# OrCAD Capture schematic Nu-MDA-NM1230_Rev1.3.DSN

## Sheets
1 Connect: size A4; title: Nu-MDA-NM1230_Connect & OP; rev: V1.3
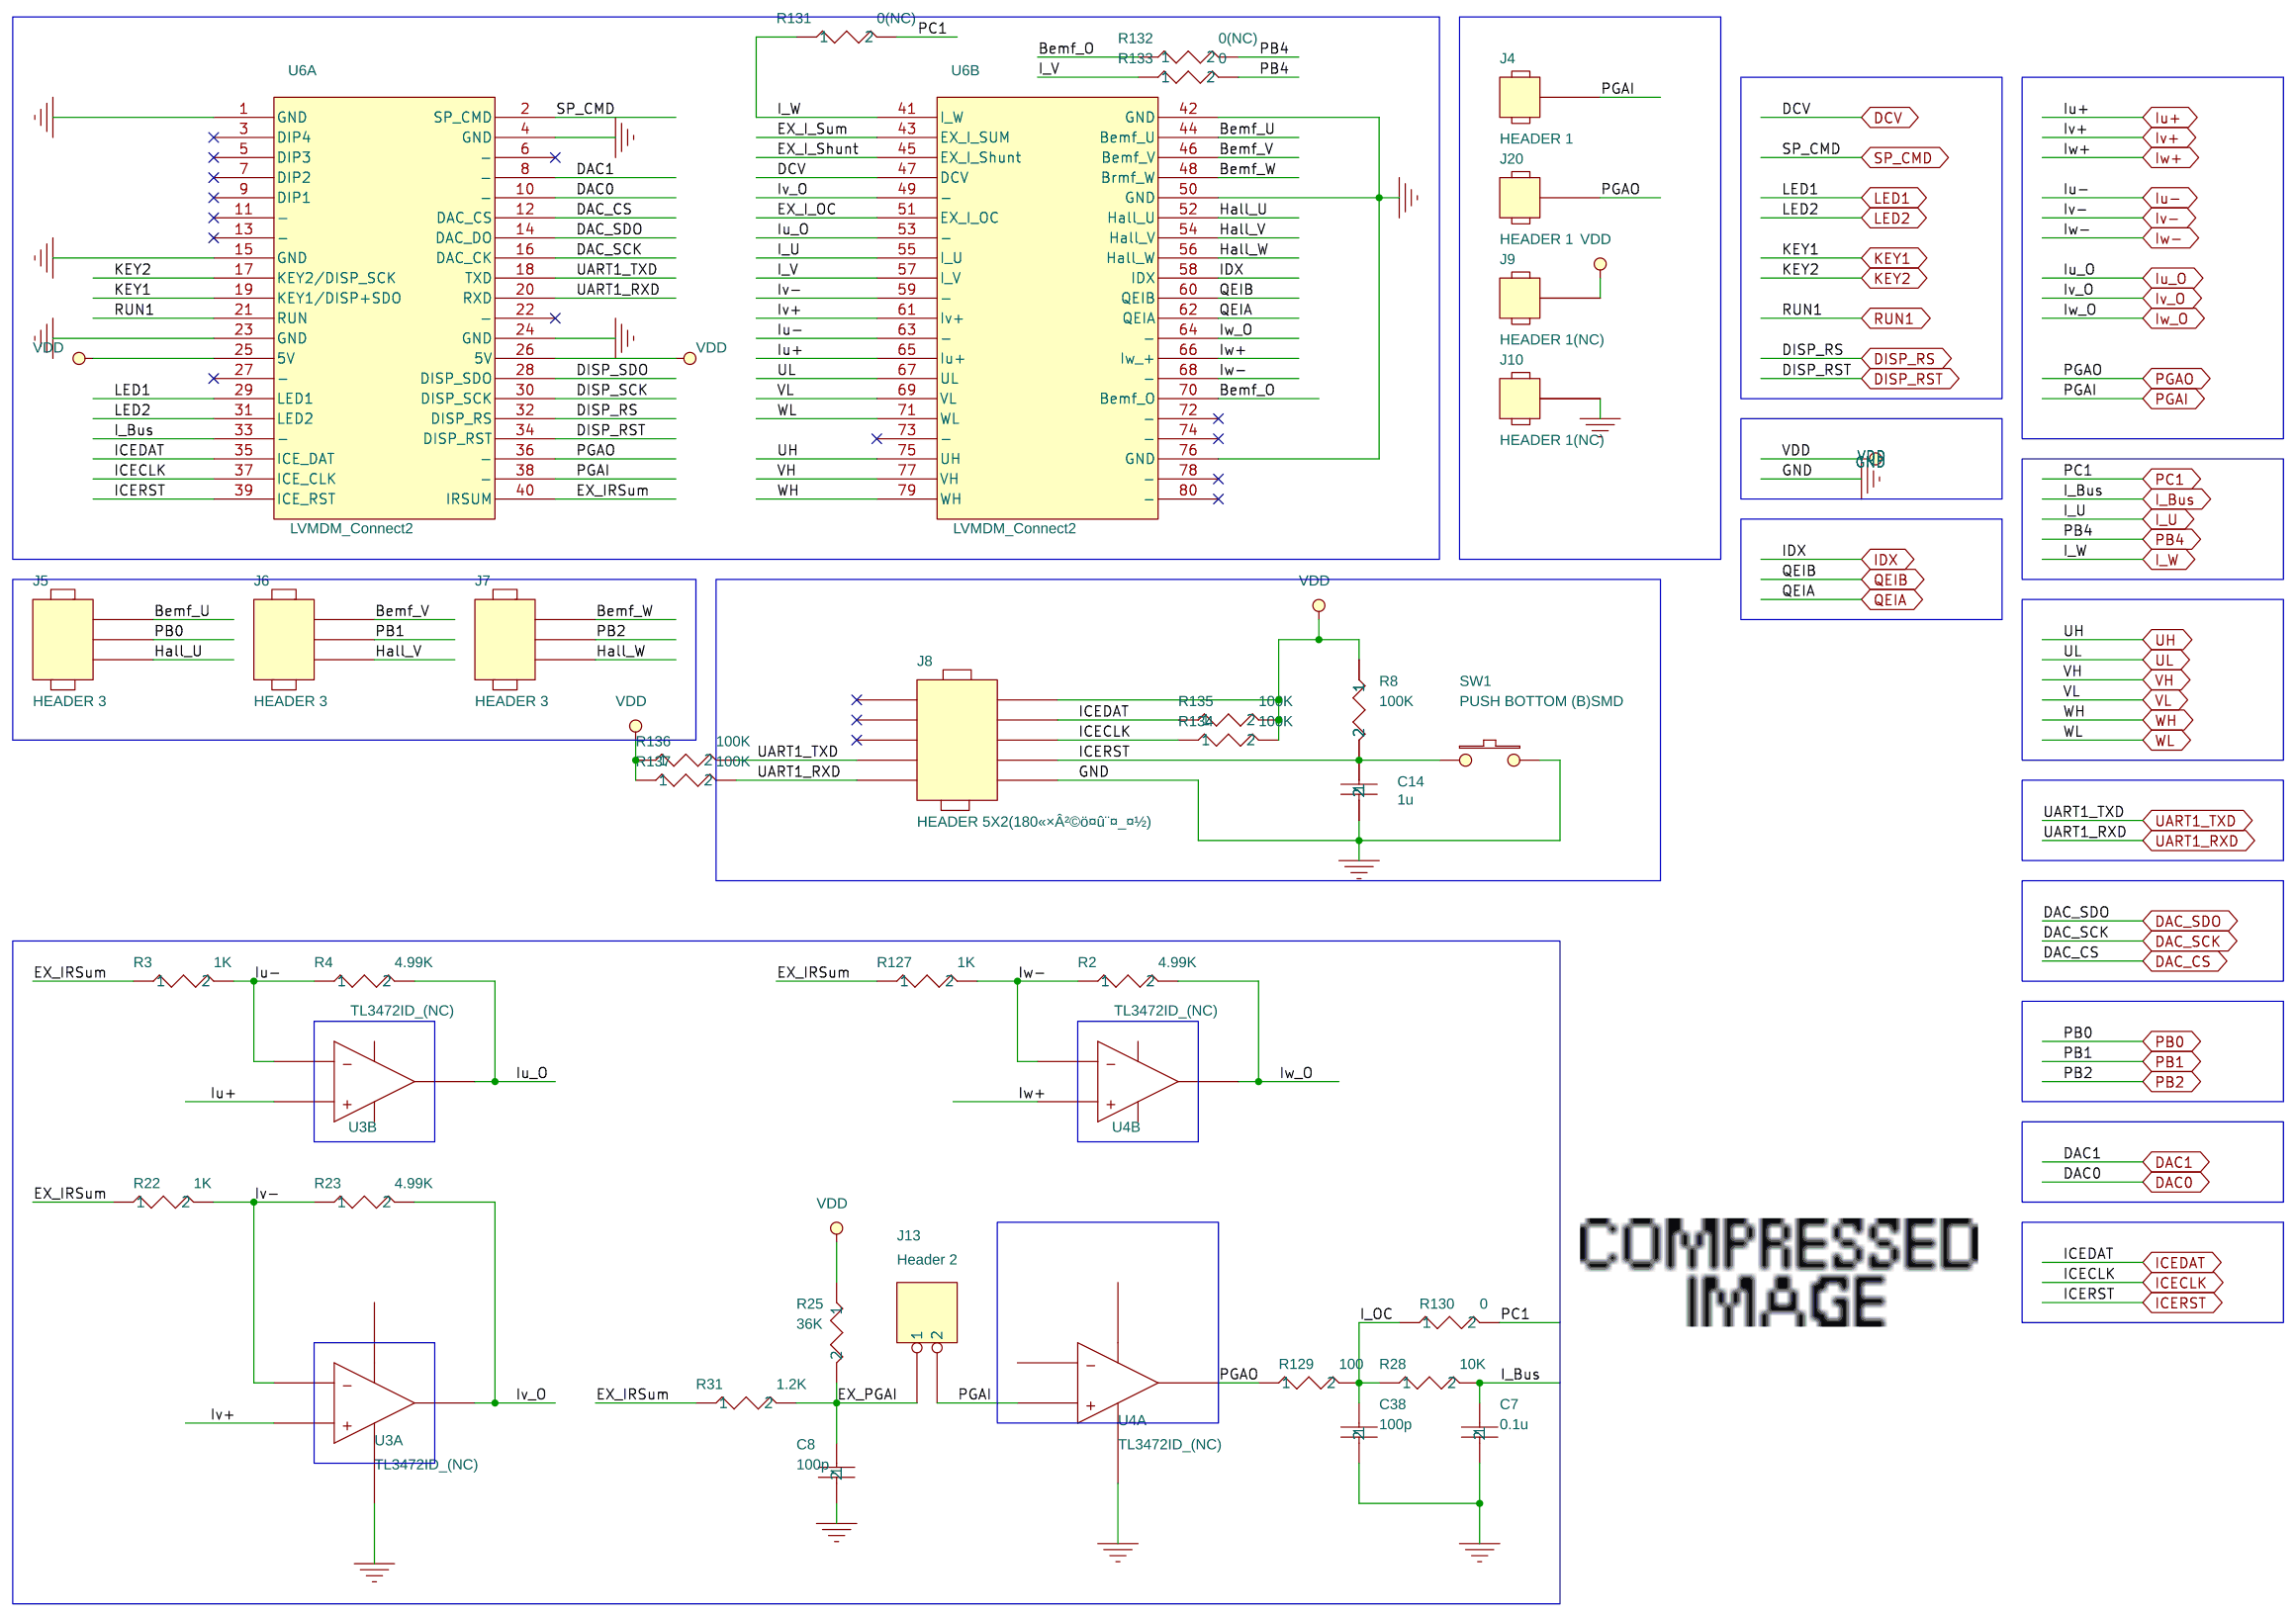
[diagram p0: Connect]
2 NM1230: size A3; title: Nu-MDA-NM1230
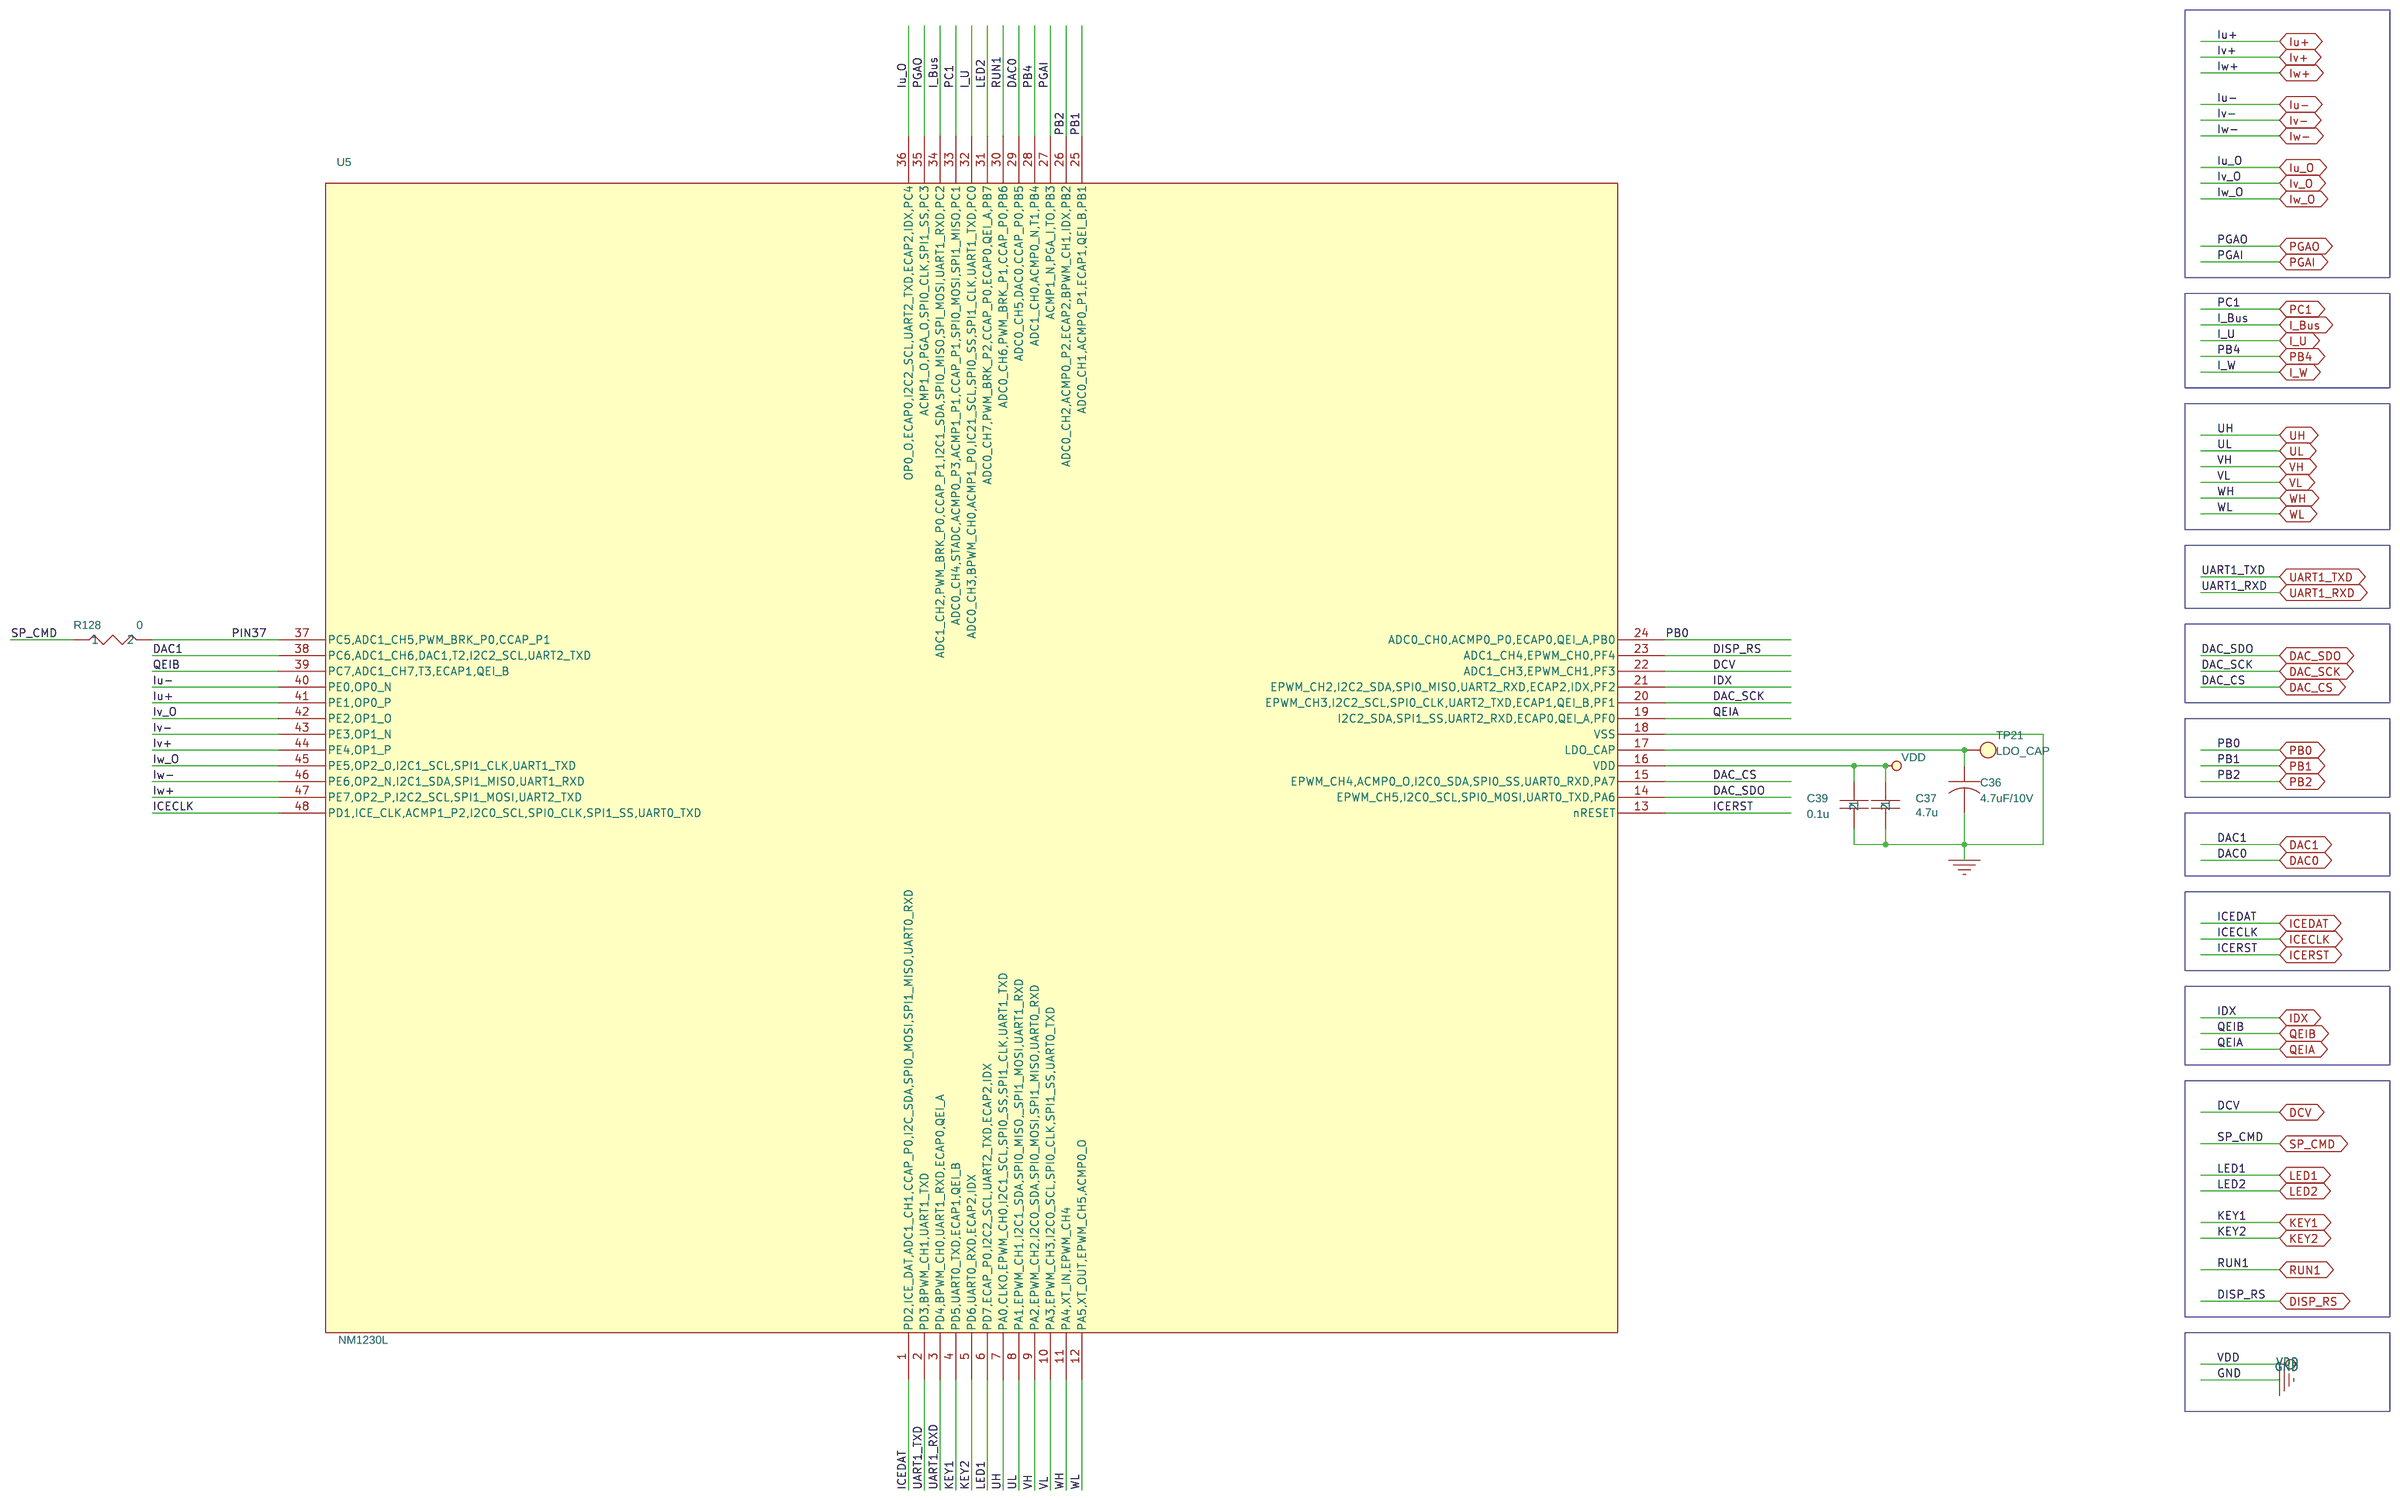
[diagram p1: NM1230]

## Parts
sheet Connect
C7  0.1u  [C0603]
C8  100p  [C0603]
C14  1u  [C0603]
C38  100p  [C0603]
J4  HEADER 1  [sip-1p]
J5  HEADER 3  [HEADER3]
J6  HEADER 3  [HEADER3]
J7  HEADER 3  [HEADER3]
J8  HEADER 5X2(180«×Â²©ö¤û¨¤_¤½)  [header2x5]
J9  HEADER 1(NC)  [sip-1p]
J10  HEADER 1(NC)  [sip-1p]
J13  Header 2  [SIP-2P]
J20  HEADER 1  [sip-1p]
R2  4.99K  [R0603]
R3  1K  [R0603]
R4  4.99K  [R0603]
R8  100K  [R0603]
R22  1K  [R0603]
R23  4.99K  [R0603]
R25  36K  [R0603]
R28  10K  [R0603]
R31  1.2K  [R0603]
R127  1K  [R0603]
R129  100  [R0603]
R130  0  [R0603]
R131  0(NC)  [R0603]
R132  0(NC)  [R0603]
R133  0  [R0603]
R134  100K  [R0603]
R135  100K  [R0603]
R136  100K  [R0603]
R137  100K  [R0603]
SW1  PUSH BOTTOM (B)SMD  [SW_SMD_HSM]
U3  TL3472ID_(NC)  (sections A,B)
U4  TL3472ID_(NC)  (sections A,B)
U6  LVMDM_Connect2  [LVMDM_Connect]  (sections A,B)
sheet NM1230
C36  4.7uF/10V  [CAP_DIP5X11]
C37  4.7u  [C0603]
C39  0.1u  [C0603]
R128  0  [R0603]
TP21  LDO_CAP  [TEST_POINT_2MM_SMD]
U5  NM1230L  [LQFP-48]

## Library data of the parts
C7 = C_0.1u
C8 = C_20p
C14 C39 = C_1u
C38 = C_0.1u_1
J4 J9 J10 J20 = HEADER_1
J5-J7 = HEADER_3
J8 = HEADER_5X2
J13 = Header_0_ohm
R2 = R_33_4
R3 = R_33_2
R4 = R_33_5
R8 = R_100K_4
R22 = R_33_1
R23 = R_33
R25 = R_10K
R28 = R_1K_3
R31 = R_33_6
R127 = R_33_3
R129 = R_1K_5
R130 = R_1K_2
R128 R131 = R_1K
R132 = R_1K_1
R133 = R_1K_4
R134 = R_100K_3
R135 = R_100K_1
R136 = R_100K_2
R137 = R_100K
SW1 = PUSH_BOTTOM_(B)
U3 U4 = TL3472ID_2
U6 = LVMDM_Connect2
C36 = C_1uF_16V
C37 = C_1u_1
TP21 = T_POINT_R
U5 = NM1230L_0

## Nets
GND: C7.2 C8.2 C14.2 C36.2 C37.2 C38.2 C39.2 J8.10 J10.1 SW1.2 U3.4 U4.4 U5.18(VSS) U6.1(GND) U6.4(GND) U6.15(GND) U6.23(GND) U6.24(GND) U6.42(GND) U6.50(GND) U6.76(GND)
VDD: C37.1 C39.1 J8.2 J9.1 R8.1 R25.1 R134.2 R135.2 R136.1 R137.1 U5.16(VDD) U6.25(5V) U6.26(5V)
Bemf_O: R132.1 U6.70(Bemf_O)
Bemf_U: J5.1 U6.44(Bemf_U)
Bemf_V: J6.1 U6.46(Bemf_V)
Bemf_W: J7.1 U6.48(Brmf_W)
DAC0: U5.29(ADC0_CH5,DAC0,CCAP_P0,PB5) U6.10(-)
DAC1: U5.38(PC6,ADC1_CH6,DAC1,T2,I2C2_SCL,UART2_TXD) U6.8(-)
DAC_CS: U5.15(EPWM_CH4,ACMP0_O,I2C0_SDA,SPI0_SS,UART0_RXD,PA7) U6.12(DAC_CS)
DAC_SCK: U5.20(EPWM_CH3,I2C2_SCL,SPI0_CLK,UART2_TXD,ECAP1,QEI_B,PF1) U6.16(DAC_CK)
DAC_SDO: U5.14(EPWM_CH5,I2C0_SCL,SPI0_MOSI,UART0_TXD,PA6) U6.14(DAC_DO)
DCV: U5.22(ADC1_CH3,EPWM_CH1,PF3) U6.47(DCV)
DISP_RS: U5.23(ADC1_CH4,EPWM_CH0,PF4) U6.32(DISP_RS)
DISP_RST: U6.34(DISP_RST)
DISP_SCK: U6.30(DISP_SCK)
DISP_SDO: U6.28(DISP_SDO)
EX_I_OC: U6.51(EX_I_OC)
EX_I_Shunt: U6.45(EX_I_Shunt)
EX_I_Sum: U6.43(EX_I_SUM)
EX_IRSum: R3.1 R22.1 R31.1 R127.1 U6.40(IRSUM)
EX_PGAI: C8.1 J13.1 R25.2 R31.2
Hall_U: J5.3 U6.52(Hall_U)
Hall_V: J6.3 U6.54(Hall_V)
Hall_W: J7.3 U6.56(Hall_W)
I_Bus: C7.1 R28.2 U5.34(ADC1_CH2,PWM_BRK_P0,CCAP_P1,I2C1_SDA,SPI0_MISO,SPI_MOSI,UART1_RXD,PC2) U6.33(-)
I_OC: C38.1 R28.1 R129.2 R130.1
I_U: U5.32(ADC0_CH3,BPWM_CH0,ACMP1_P0,IC21_SCL,SPI0_SS,SPI1_CLK,UART1_TXD,PC0) U6.55(I_U)
I_V: R133.1 U6.57(I_V)
I_W: R131.1 U6.41(I_W)
ICECLK: J8.6 R134.1 U5.48(PD1,ICE_CLK,ACMP1_P2,I2C0_SCL,SPI0_CLK,SPI1_SS,UART0_TXD) U6.37(ICE_CLK)
ICEDAT: J8.4 R135.1 U5.1(PD2,ICE_DAT,ADC1_CH1,CCAP_P0,I2C_SDA,SPI0_MOSI,SPI1_MISO,UART0_RXD) U6.35(ICE_DAT)
ICERST: C14.1 J8.8 R8.2 SW1.1 U5.13(nRESET) U6.39(ICE_RST)
IDX: U5.21(EPWM_CH2,I2C2_SDA,SPI0_MISO,UART2_RXD,ECAP2,IDX,PF2) U6.58(IDX)
Iu+: U3.5 U5.41(PE1,OP0_P) U6.65(Iu+)
Iu-: R3.2 R4.1 U3.6 U5.40(PE0,OP0_N) U6.63(-)
Iu_O: R4.2 U3.7 U5.36(OP0_O,ECAP0,I2C2_SCL,UART2_TXD,ECAP2,IDX,PC4) U6.53(-)
Iv+: U3.3 U5.44(PE4,OP1_P) U6.61(Iv+)
Iv-: R22.2 R23.1 U3.2 U5.43(PE3,OP1_N) U6.59(-)
Iv_O: R23.2 U3.1 U5.42(PE2,OP1_O) U6.49(-)
Iw+: U4.5 U5.47(PE7,OP2_P,I2C2_SCL,SPI1_MOSI,UART2_TXD) U6.66(Iw_+)
Iw-: R2.1 R127.2 U4.6 U5.46(PE6,OP2_N,I2C1_SDA,SPI1_MISO,UART1_RXD) U6.68(-)
Iw_O: R2.2 U4.7 U5.45(PE5,OP2_O,I2C1_SCL,SPI1_CLK,UART1_TXD) U6.64(-)
KEY1: U5.4(PD5,UART0_TXD,ECAP1,QEI_B) U6.19(KEY1/DISP+SDO)
KEY2: U5.5(PD6,UART0_RXD,ECAP2,IDX) U6.17(KEY2/DISP_SCK)
LED1: U5.6(PD7,ECAP_P0,I2C2_SCL,UART2_TXD,ECAP2,IDX) U6.29(LED1)
LED2: U5.31(ADC0_CH7,PWM_BRK_P2,CCAP_P0,ECAP0,QEI_A,PB7) U6.31(LED2)
PB0: J5.2 U5.24(ADC0_CH0,ACMP0_P0,ECAP0,QEI_A,PB0)
PB1: J6.2 U5.25(ADC0_CH1,ACMP0_P1,ECAP1,QEI_B,PB1)
PB2: J7.2 U5.26(ADC0_CH2,ACMP0_P2,ECAP2,BPWM_CH1,IDX,PB2)
PB4: R132.2 R133.2 U5.28(ADC1_CH0,ACMP0_N,T1,PB4)
PC1: R130.2 R131.2 U5.33(ADC0_CH4,STADC,ACMP0_P3,ACMP1_P1,CCAP_P1,SPI0_MOSI,SPI1_MISO,PC1)
PGAI: J4.1 J13.2 U4.3 U5.27(ACMP1_N,PGA_I,TO,PB3) U6.38(-)
PGAO: J20.1 R129.1 U4.1 U5.35(ACMP1_O,PGA_O,SPI0_CLK,SPI1_SS,PC3) U6.36(-)
PIN37: R128.2 U5.37(PC5,ADC1_CH5,PWM_BRK_P0,CCAP_P1)
QEIA: U5.19(I2C2_SDA,SPI1_SS,UART2_RXD,ECAP0,QEI_A,PF0) U6.62(QEIA)
QEIB: U5.39(PC7,ADC1_CH7,T3,ECAP1,QEI_B) U6.60(QEIB)
RUN1: U5.30(ADC0_CH6,PWM_BRK_P1,CCAP_P0,PB6) U6.21(RUN)
SP_CMD: R128.1 U6.2(SP_CMD)
UART1_RXD: J8.9 R137.2 U5.3(PD4,BPWM_CH0,UART1_RXD,ECAP0,QEI_A) U6.20(RXD)
UART1_TXD: J8.7 R136.2 U5.2(PD3,BPWM_CH1,UART1_TXD) U6.18(TXD)
UH: U5.7(PA0,CLKO,EPWM_CH0,I2C1_SCL,SPI0_SS,SPI1_CLK,UART1_TXD) U6.75(UH)
UL: U5.8(PA1,EPWM_CH1,I2C1_SDA,SPI0_MISO,_SPI1_MOSI,UART1_RXD) U6.67(UL)
VH: U5.9(PA2,EPWM_CH2,I2C0_SDA,SPI0_MOSI,SPI1_MISO,UART0_RXD) U6.77(VH)
VL: U5.10(PA3,EPWM_CH3,I2C0_SCL,SPI0_CLK,SPI1_SS,UART0_TXD) U6.69(VL)
WH: U5.11(PA4,XT_IN,EPWM_CH4) U6.79(WH)
WL: U5.12(PA5,XT_OUT,EPWM_CH5,ACMP0_O) U6.71(WL)
N46118: C36.1 TP21.1(TP) U5.17(LDO_CAP)

Not connected (* = marked no-connect by the designer): J8 1* 3* 5*; U3 8; U4 2 8; U6 3(DIP4)* 5(DIP3)* 6(-)* 7(DIP2)* 9(DIP1)* 11(-)* 13(-)* 22(-)* 27(-)* 72(-)* 73(-)* 74(-)* 78(-)* 80(-)*
